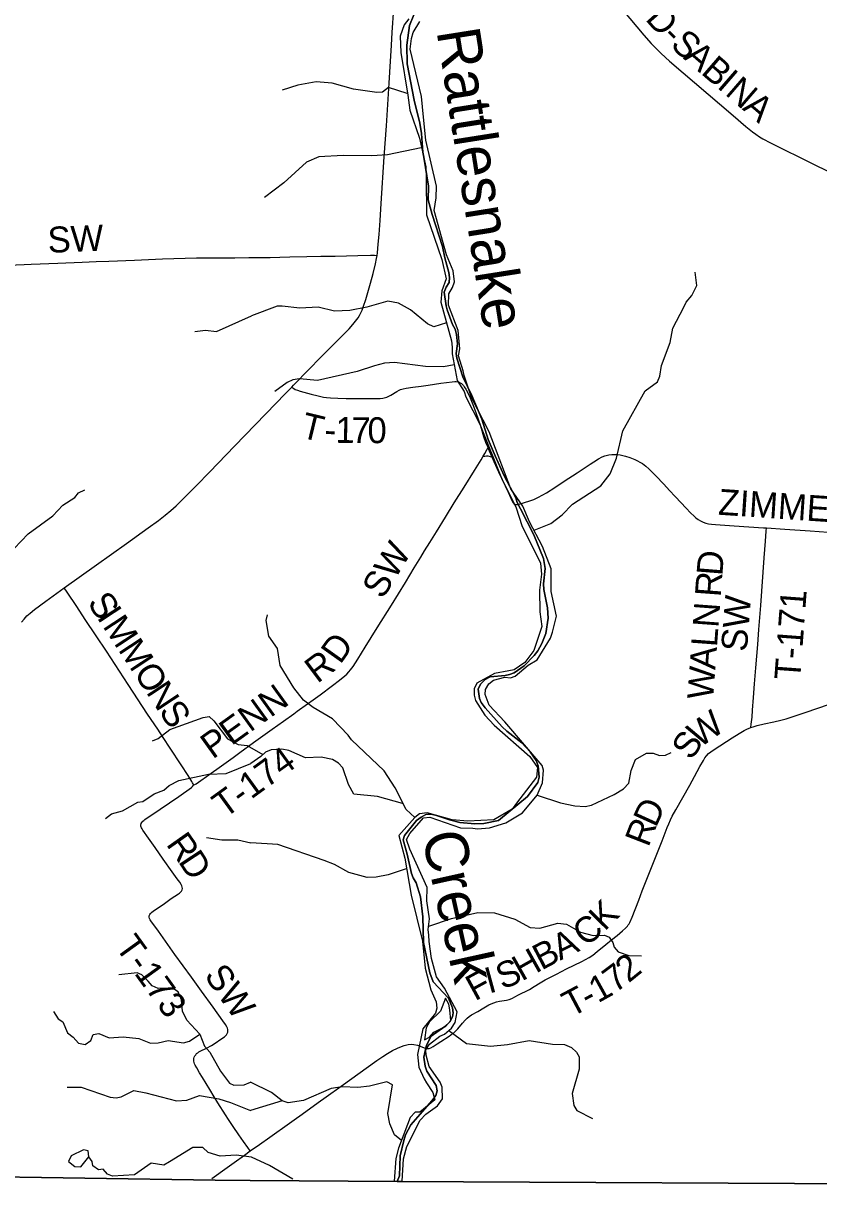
# Model space of a CAD drawing. Extents: x -51392 to 1635000, y 156707 to 696232.
# Drawn here: x 119003 to 128219, y 428826 to 442411 of the extents above; entities that cross this region are included whole.
import ezdxf

# ---------------------------------------------------------------- set-up
doc = ezdxf.new("R2010")
doc.units = 0
for name, color, linetype in [('GM_X_Adjacent_County', 7, 'Continuous'), ('GM_X_County', 7, 'Continuous'), ('GM_X_County_Road', 7, 'Continuous'), ('GM_X_County_Road_Text', 7, 'Continuous'), ('GM_X_Major_River', 7, 'Continuous'), ('GM_X_Major_River_Text', 7, 'Continuous'), ('GM_X_Minor_River', 7, 'Continuous'), ('GM_X_Township', 7, 'Continuous'), ('GM_X_Township_Road', 7, 'Continuous'), ('GM_X_Township_Road_Text', 7, 'Continuous')]:
    doc.layers.add(name, color=color, linetype=linetype)

msp = doc.modelspace()

# ---------------------------------------------------------------- linework, layer by layer
at = {"layer": 'GM_X_Adjacent_County'}
msp.add_lwpolyline([(104828, 429256), (108959, 429193), (114698, 429106), (118200, 429053), (121225, 429006), (121630, 429000), (123335, 428991), (129473, 428959), (134438, 428933), (140234, 428904), (140363, 428903), (142841, 428889), (147184, 428866), (150230, 428850), (152105, 428841), (155079, 428826)], dxfattribs=at)
at = {"layer": 'GM_X_County'}
msp.add_lwpolyline([(155079, 428826), (152105, 428841), (150230, 428850), (147184, 428866), (142841, 428889), (140363, 428903), (140234, 428904), (134438, 428933), (129473, 428959), (123335, 428991), (121630, 429000), (121225, 429006), (118200, 429053), (114698, 429106), (108959, 429193), (104828, 429256)], dxfattribs=at)
at = {"layer": 'GM_X_County_Road'}
for points in [[(123102, 439722), (123106, 439753), (123116, 439851), (123125, 439966), (123137, 440129), (123149, 440326), (123185, 440866), (123209, 441226), (123240, 441717), (123249, 441848), (123269, 442159), (123278, 442306), (123296, 442584)], [(125949, 442564), (126193, 442276), (126280, 442178), (126336, 442119), (126395, 442062), (126493, 441975), (127229, 441346), (127377, 441218), (127454, 441155), (127493, 441126), (127533, 441098), (127575, 441073), (127662, 441027), (128162, 440780), (128500, 440613)], [(122112, 438196), (122133, 438218), (122316, 438406), (122442, 438535), (122523, 438617), (122638, 438733), (122731, 438826), (122778, 438872), (122822, 438921), (122853, 438959), (122882, 439000), (122899, 439028), (122914, 439057), (122927, 439087), (122945, 439134), (122970, 439212), (123026, 439401), (123056, 439512), (123083, 439624), (123096, 439688), (123102, 439722)], [(119476, 435868), (119849, 436135), (120022, 436260), (120196, 436384), (120450, 436565), (120569, 436652), (120647, 436712), (120710, 436765), (120771, 436820), (120842, 436888), (121004, 437051), (121164, 437216), (121449, 437510), (121814, 437888), (122042, 438124), (122112, 438196)], [(118980, 435470), (119010, 435508), (119043, 435544), (119080, 435577), (119130, 435618), (119263, 435715), (119476, 435868)]]:
    msp.add_lwpolyline(points, dxfattribs=at)
at = {"layer": 'GM_X_Major_River'}
msp.add_line((123299, 428993), (123394, 428992), dxfattribs=at)
for points in [[(123468, 442466), (123414, 442396), (123370, 442262), (123377, 442075), (123457, 441578), (123483, 441405), (123592, 441081), (123666, 440748), (123672, 440620), (123673, 440193), (123854, 439676), (123904, 439451), (123851, 439313), (123842, 439179), (123966, 438733), (123974, 438658), (123971, 438582), (124030, 438271), (124111, 438146), (124131, 438082), (124292, 437766), (124543, 437142), (124712, 436796), (124779, 436593), (124995, 436154), (125008, 436028), (124984, 435843), (124990, 435593), (125013, 435420), (124918, 435144), (124815, 435003), (124692, 434920), (124629, 434908), (124461, 434877), (124258, 434765), (124229, 434701), (124228, 434627), (124244, 434563), (124349, 434395), (124460, 434280)], [(124400, 434511), (124355, 434632), (124357, 434690), (124398, 434756), (124452, 434801), (124581, 434836), (124647, 434826), (124703, 434845), (124854, 434972), (124959, 435036), (125113, 435287), (125134, 435355), (125182, 435543), (125118, 435826), (125121, 436089), (125021, 436348), (124867, 436636), (124790, 436815), (124654, 437019), (124505, 437405), (124402, 437679), (124197, 438077), (124113, 438330), (124099, 438383), (124045, 438558), (124060, 438640), (124041, 438852), (123928, 439144), (123933, 439278), (123976, 439352), (124000, 439416), (123983, 439544), (123905, 439731), (123765, 440244), (123787, 440390), (123792, 440526), (123666, 441059), (123641, 441325), (123617, 441564), (123485, 442113), (123500, 442235), (123521, 442307), (123596, 442434)], [(123394, 428992), (123408, 429251), (123445, 429395), (123602, 429701), (123665, 429768), (123802, 429867), (123861, 429947), (123856, 430083), (123833, 430142), (123704, 430323), (123669, 430454), (123668, 430516), (123710, 430582), (123829, 430673), (123883, 430695), (123964, 430768), (124007, 430832), (124030, 430954), (123882, 431230), (123789, 431363), (123733, 431574), (123707, 431769), (123701, 431845), (123694, 431909), (123711, 432033), (123677, 432244), (123682, 432396), (123480, 432841), (123443, 432954), (123483, 433023), (123639, 433203), (123713, 433210), (124069, 433089), (124213, 433083), (124267, 433077), (124405, 433088), (124594, 433146), (124787, 433263), (124957, 433468), (125021, 433608), (125032, 433758), (125016, 433810), (124584, 434317), (124400, 434511)], [(124460, 434280), (124871, 433916), (124960, 433789), (124949, 433677), (124718, 433376), (124667, 433306), (124454, 433180), (124154, 433166), (123971, 433180), (123682, 433262), (123594, 433249), (123539, 433207), (123355, 432998), (123423, 432737), (123495, 432306), (123629, 431773), (123660, 431462), (123724, 431211), (123785, 431072), (123794, 430998), (123779, 430940), (123632, 430759), (123569, 430461), (123584, 430316), (123647, 430181), (123676, 430131), (123747, 430020), (123773, 429936), (123597, 429793), (123543, 429791), (123486, 429732), (123349, 429374), (123318, 429256), (123299, 428993)], [(123893, 431113), (123836, 430964), (123708, 430838), (123672, 430769), (123653, 430630), (123711, 430662), (123758, 430722), (123868, 430773)], [(123868, 430773), (123896, 430787), (123955, 430856), (123946, 430979), (123935, 431045), (123893, 431113)]]:
    msp.add_lwpolyline(points, dxfattribs=at)
at = {"layer": 'GM_X_Minor_River'}
msp.add_line((123299, 428993), (123394, 428992), dxfattribs=at)
for points in [[(123451, 441599), (123233, 441668), (123164, 441614), (123098, 441611), (122828, 441651), (122581, 441719), (122395, 441735), (122184, 441697), (122001, 441636)], [(123614, 440971), (123222, 440890), (123040, 440875), (122707, 440880), (122427, 440867), (122284, 440804), (122022, 440563), (121796, 440395)], [(124922, 436540), (125117, 436616), (125248, 436717), (125367, 436838), (125696, 437052), (125803, 437192), (125877, 437373), (125952, 437689), (126208, 438154), (126351, 438259), (126380, 438323), (126397, 438445), (126499, 438713), (126531, 438881), (126657, 439123), (126684, 439181), (126749, 439258), (126810, 439374), (126787, 439529)], [(123906, 438943), (123759, 438893), (123688, 438929), (123491, 439092), (123351, 439171), (123227, 439194), (122982, 439122), (122786, 439083), (122609, 439077), (122418, 439123), (122205, 439110), (122003, 439134), (121943, 439133), (121645, 439023)], [(120988, 438839), (121112, 438857), (121239, 438841), (121645, 439023)], [(123996, 438456), (123871, 438431), (123663, 438435), (123305, 438480), (123187, 438473), (123072, 438444), (122870, 438377), (122410, 438273), (122202, 438293), (122124, 438279), (122061, 438250), (121916, 438145)], [(118895, 436327), (119056, 436495), (119342, 436704), (119460, 436828), (119597, 436918), (119641, 436972), (119715, 437004)], [(123539, 433207), (123438, 433302), (123312, 433550), (123185, 433748), (122806, 434108), (122768, 434164), (122586, 434350), (122361, 434482), (122247, 434569), (122136, 434709), (121978, 434971), (121948, 435167), (121847, 435309), (121817, 435493), (121831, 435555)], [(120497, 434095), (120563, 434125), (120699, 434227), (121086, 434366), (121154, 434378), (121208, 434330), (121368, 434118), (121490, 434054), (121596, 434044)], [(121596, 434044), (121776, 433938), (121774, 433940)], [(121668, 434041), (121668, 434041)], [(123398, 433370), (123107, 433450), (122833, 433478), (122771, 433589), (122703, 433784), (122655, 433838), (122586, 433879), (122454, 433908), (122273, 433900), (122078, 433986), (121998, 434000), (121874, 433993), (121807, 433966), (121753, 433916), (121637, 433833)], [(124957, 433468), (125229, 433377), (125393, 433344), (125515, 433337), (125587, 433350), (125851, 433474), (125959, 433540), (126018, 433607), (126047, 433751), (126096, 433879), (126223, 433954), (126301, 433954), (126375, 433927), (126443, 433932), (126510, 433962)], [(119953, 433196), (120024, 433252), (120150, 433284), (120328, 433386), (120386, 433394), (120518, 433482), (120630, 433524), (120693, 433578), (120803, 433636), (121149, 433711), (121353, 433719), (121637, 433833)], [(121126, 432976), (121304, 432950), (121488, 432950), (121637, 432914)], [(121565, 432927), (121564, 432927)], [(123438, 432615), (123231, 432544), (123092, 432518), (122986, 432514), (122776, 432570), (122607, 432664), (122489, 432709), (121950, 432894), (121637, 432914)], [(123700, 431948), (123963, 432039), (124268, 432107), (124463, 432105), (124698, 432031), (124876, 431935), (124988, 431924), (125195, 431983), (125299, 431972), (125458, 431878), (125606, 431841), (125738, 431846), (125792, 431821), (125835, 431759), (125849, 431706), (125895, 431652), (126018, 431609), (126168, 431603)], [(121049, 430695), (120897, 430859), (120845, 430963), (120833, 431094), (120797, 431186), (120729, 431230), (120563, 431228), (120495, 431256), (120447, 431310), (120375, 431384), (120319, 431407), (120107, 431385)], [(119350, 430961), (119404, 430875), (119458, 430838), (119512, 430714), (119580, 430664), (119642, 430592), (119718, 430576), (119782, 430624), (119812, 430694), (119878, 430704), (119996, 430656), (120158, 430666), (120340, 430645), (120476, 430591), (120564, 430597), (120682, 430623), (120856, 430595), (120926, 430617), (121049, 430695), (121103, 430559), (121164, 430488), (121288, 430270), (121390, 430130), (121442, 430104), (121560, 430111), (121635, 430139)], [(123933, 430738), (124139, 430590), (124415, 430558), (124613, 430576), (124866, 430624), (125136, 430580), (125276, 430579), (125356, 430542), (125414, 430487), (125443, 430433), (125446, 430290), (125363, 430008), (125382, 429870), (125418, 429814), (125599, 429720)], [(123383, 429463), (123304, 429531), (123251, 429658), (123228, 429776), (123279, 430110), (123214, 430145), (123015, 430093), (122877, 430078), (122698, 430085), (122570, 430068), (122250, 429927), (122070, 429902), (122002, 429925), (121877, 430022), (121635, 430139)], [(119509, 430081), (119671, 430081), (120009, 429967), (120077, 429959), (120135, 429971), (120283, 430044), (120421, 430018), (120775, 429926), (120895, 429932), (121044, 429986), (121266, 429947), (121404, 429905), (121636, 429813)], [(122002, 429925), (121636, 429813)], [(121646, 429271), (121467, 429296), (121281, 429282), (121143, 429327), (121083, 429383), (120967, 429385), (120696, 429219), (120630, 429177), (120482, 429201), (120288, 429067), (120034, 429053), (119976, 429075), (119926, 429133), (119874, 429123), (119808, 429170), (119798, 429222), (119760, 429276), (119752, 429346), (119698, 429358), (119554, 429288), (119525, 429222), (119599, 429162), (119669, 429160), (119760, 429276)], [(122126, 429016), (121855, 429176), (121646, 429271)]]:
    msp.add_lwpolyline(points, dxfattribs=at)
at = {"layer": 'GM_X_Township'}
for points in [[(123526, 442511), (123479, 442389), (123446, 442159), (123452, 441941), (123533, 441520), (123596, 441255), (123616, 441135), (123631, 440918), (123643, 440860), (123696, 440527), (123693, 440367), (123741, 440195), (123860, 439826), (123886, 439695), (123933, 439525), (123941, 439465), (123937, 439407), (123903, 439353), (123880, 439295), (123902, 439140), (123914, 439090), (123977, 438920), (124005, 438866), (124021, 438805), (124035, 438699), (124019, 438585), (124026, 438531), (124096, 438316), (124199, 438098), (124315, 437825), (124388, 437590), (124470, 437398), (124575, 437167), (124709, 436912), (124727, 436858), (124763, 436786), (124918, 436485), (125031, 436208), (125051, 436095), (125032, 435917), (125034, 435849), (125079, 435639), (125083, 435518), (125056, 435340), (125012, 435224), (124964, 435138), (124923, 435086), (124807, 434964), (124692, 434886), (124638, 434865), (124588, 434855), (124414, 434839), (124356, 434807), (124301, 434755), (124273, 434695), (124287, 434589), (124307, 434539), (124355, 434479), (124552, 434260), (124606, 434208), (124778, 434073), (124876, 433970), (124912, 433920), (124944, 433868), (124968, 433808), (124981, 433675), (124967, 433613), (124846, 433450), (124511, 433172), (124338, 433137), (124236, 433133), (124062, 433149), (123940, 433180), (123778, 433237), (123725, 433245), (123665, 433241), (123611, 433213), (123557, 433173), (123420, 433001), (123404, 432949), (123450, 432785), (123499, 432560), (123519, 432510), (123555, 432452), (123604, 432287), (123632, 432057), (123639, 431758), (123712, 431408), (123752, 431305), (123929, 431114), (123975, 431002), (123983, 430946), (123977, 430896), (123945, 430840), (123888, 430784), (123728, 430674), (123673, 430570), (123656, 430483), (123645, 430430), (123660, 430326), (123678, 430270), (123786, 430103), (123800, 430039), (123782, 429985), (123735, 429925), (123494, 429645), (123433, 429531), (123411, 429465), (123371, 429287), (123362, 429055), (123335, 428991), (121630, 429000), (121225, 429006), (118200, 429053)], [(129473, 428959), (123335, 428991), (123362, 429055), (123371, 429287), (123411, 429465), (123433, 429531), (123494, 429645), (123735, 429925), (123782, 429985), (123800, 430039), (123786, 430103), (123678, 430270), (123660, 430326), (123645, 430430), (123656, 430483), (123673, 430570), (123728, 430674), (123888, 430784), (123945, 430840), (123977, 430896), (123983, 430946), (123975, 431002), (123929, 431114), (123752, 431305), (123712, 431408), (123639, 431758), (123632, 432057), (123604, 432287), (123555, 432452), (123519, 432510), (123499, 432560), (123450, 432785), (123404, 432949), (123420, 433001), (123557, 433173), (123611, 433213), (123665, 433241), (123725, 433245), (123778, 433237), (123940, 433180), (124062, 433149), (124236, 433133), (124338, 433137), (124511, 433172), (124846, 433450), (124967, 433613), (124981, 433675), (124968, 433808), (124944, 433868), (124912, 433920), (124876, 433970), (124778, 434073), (124606, 434208), (124552, 434260), (124355, 434479), (124307, 434539), (124287, 434589), (124273, 434695), (124301, 434755), (124356, 434807), (124414, 434839), (124588, 434855), (124638, 434865), (124692, 434886), (124807, 434964), (124923, 435086), (124964, 435138), (125012, 435224), (125056, 435340), (125083, 435518), (125079, 435639), (125034, 435849), (125032, 435917), (125051, 436095), (125031, 436208), (124918, 436485), (124763, 436786), (124727, 436858), (124709, 436912), (124575, 437167), (124470, 437398), (124388, 437590), (124315, 437825), (124199, 438098), (124096, 438316), (124026, 438531), (124019, 438585), (124035, 438699), (124021, 438805), (124005, 438866), (123977, 438920), (123914, 439090), (123902, 439140), (123880, 439295), (123903, 439353), (123937, 439407), (123941, 439465), (123933, 439525), (123886, 439695), (123860, 439826), (123741, 440195), (123693, 440367), (123696, 440527), (123643, 440860), (123631, 440918), (123616, 441135), (123596, 441255), (123533, 441520), (123452, 441941), (123446, 442159), (123479, 442389), (123526, 442511)]]:
    msp.add_lwpolyline(points, dxfattribs=at)
at = {"layer": 'GM_X_Township_Road'}
for points in [[(118732, 439606), (119010, 439618), (119092, 439621), (119403, 439634), (119682, 439645), (119846, 439652), (119993, 439657), (120288, 439667), (120452, 439675), (120616, 439681), (120878, 439691), (121009, 439694), (121206, 439695), (121451, 439696), (121615, 439697), (121861, 439699), (121976, 439703), (122090, 439706), (122287, 439710), (122451, 439713), (122615, 439715), (122746, 439719), (122877, 439723), (123024, 439726), (123072, 439727), (123102, 439722)], [(122112, 438196), (122136, 438180), (122153, 438170), (122180, 438159), (122212, 438149), (122338, 438114), (122417, 438094), (122481, 438079), (122514, 438074), (122563, 438070), (122645, 438067), (122743, 438066), (122890, 438066), (123005, 438064), (123087, 438064), (123136, 438065), (123169, 438069), (123185, 438072), (123216, 438081), (123231, 438088), (123260, 438102), (123330, 438146), (123359, 438161), (123374, 438168), (123389, 438173), (123405, 438178), (123437, 438185), (123517, 438197), (123614, 438208), (123695, 438220), (123841, 438241), (123971, 438258), (124004, 438261), (124020, 438261), (124036, 438259), (124052, 438254), (124066, 438247), (124080, 438238), (124092, 438227), (124103, 438214), (124113, 438201), (124130, 438173), (124160, 438115), (124181, 438071), (124212, 437995), (124247, 437903), (124275, 437826), (124300, 437748), (124337, 437622), (124359, 437560), (124384, 437500), (124387, 437494)], [(124333, 437395), (124351, 437426), (124374, 437469), (124387, 437494)], [(124387, 437494), (124433, 437387)], [(120973, 433586), (120988, 433590), (121005, 433597), (121180, 433722), (121273, 433789), (121432, 433904), (121512, 433962), (121671, 434077), (121751, 434134), (121884, 434230), (122017, 434326), (122137, 434411), (122176, 434440), (122295, 434526), (122362, 434573), (122442, 434631), (122586, 434738), (122665, 434798), (122728, 434850), (122752, 434871), (122775, 434895), (122795, 434920), (122824, 434960), (122877, 435043), (122964, 435182), (123103, 435405), (123268, 435669), (123432, 435933), (123483, 436017), (123533, 436101), (123610, 436227), (123653, 436297), (123713, 436394), (123790, 436520), (123894, 436687), (123997, 436854), (124110, 437036), (124232, 437230), (124309, 437355), (124333, 437395)], [(124333, 437395), (124352, 437397), (124371, 437399), (124387, 437398), (124412, 437393), (124433, 437387)], [(124433, 437387), (124456, 437335), (124509, 437214), (124550, 437125), (124622, 436978), (124669, 436873), (124677, 436859), (124687, 436846), (124701, 436837), (124717, 436834), (124733, 436835), (124741, 436838)], [(124741, 436838), (124749, 436840), (124874, 436878), (124920, 436895), (124965, 436916), (125022, 436947), (125065, 436972), (125161, 437034), (125270, 437106), (125421, 437204), (125504, 437256), (125572, 437302), (125613, 437329), (125668, 437364), (125711, 437388), (125741, 437400), (125773, 437409), (125789, 437412), (125821, 437416), (125854, 437417), (125887, 437415), (125919, 437410), (125951, 437403), (125983, 437395), (126030, 437379), (126091, 437356), (126121, 437343), (126149, 437327), (126177, 437310), (126216, 437280), (126252, 437248), (126288, 437214), (126334, 437167), (126424, 437071), (126490, 436999), (126557, 436927), (126625, 436856), (126681, 436797), (126738, 436737), (126773, 436703), (126798, 436682), (126824, 436662), (126852, 436645), (126882, 436632), (126913, 436621), (126945, 436613), (126977, 436607), (127026, 436602), (127239, 436590), (127582, 436567), (127614, 436565)], [(127435, 434250), (127439, 434290), (127448, 434371), (127455, 434453), (127466, 434598), (127478, 434756), (127493, 434943), (127514, 435215), (127527, 435385), (127549, 435667), (127589, 436216), (127603, 436412), (127612, 436526), (127614, 436565)], [(127614, 436565), (127828, 436550), (128122, 436529), (128433, 436507), (128923, 436470), (129103, 436457), (129446, 436432), (129659, 436417), (129871, 436404), (130068, 436392), (130362, 436375), (130542, 436363), (130657, 436357), (130935, 436340), (131000, 436335), (131049, 436327), (131080, 436320), (131112, 436309), (131157, 436290), (131231, 436254), (131333, 436202), (131494, 436117)], [(120973, 433586), (120973, 433592), (120971, 433597), (120964, 433611), (120955, 433625), (120911, 433694), (120830, 433818), (120704, 434010), (120623, 434134), (120560, 434230), (120441, 434407), (120217, 434750), (120064, 434983), (119964, 435134), (119847, 435312), (119720, 435504), (119621, 435654), (119511, 435818), (119476, 435868)], [(127435, 434250), (127462, 434260), (127509, 434274), (127589, 434293), (127702, 434317), (127782, 434335), (127845, 434352), (127923, 434377), (128063, 434424), (128482, 434568)], [(123669, 430532), (123687, 430529), (123704, 430531), (123724, 430537), (123753, 430553), (123800, 430586), (123842, 430611), (123937, 430675), (123977, 430704), (123990, 430714), (124014, 430736), (124037, 430760), (124090, 430823), (124123, 430859), (124146, 430882), (124171, 430902), (124198, 430920), (124270, 430960), (124340, 431001), (124397, 431035), (124426, 431049), (124456, 431061), (124487, 431071), (124519, 431078), (124600, 431091), (124632, 431100), (124662, 431112), (124706, 431134), (124735, 431150), (124867, 431216), (124924, 431248), (124993, 431292), (125050, 431325), (125181, 431393), (125298, 431453), (125475, 431538), (125519, 431561), (125561, 431586), (125602, 431614), (125653, 431654), (125755, 431738), (125819, 431789), (125883, 431840), (125946, 431893), (125982, 431926), (126004, 431950), (126014, 431963), (126023, 431977), (126031, 431991), (126057, 432051), (126135, 432250), (126176, 432357), (126261, 432571), (126405, 432937), (126464, 433091), (126482, 433136), (126502, 433181), (126524, 433225), (126564, 433297), (126647, 433438), (126728, 433581), (126782, 433683), (126844, 433799), (126884, 433870), (126902, 433898), (126922, 433924), (126944, 433948), (126969, 433969), (127010, 433997), (127217, 434130), (127300, 434182), (127357, 434216), (127386, 434231), (127416, 434244), (127435, 434250)], [(121629, 429343), (121603, 429382), (121555, 429451), (121499, 429531), (121434, 429626), (121380, 429708), (121344, 429763), (121257, 429902), (121214, 429972), (121163, 430056), (121079, 430194), (121045, 430249), (121011, 430307), (120995, 430336), (120987, 430352), (120982, 430368), (120978, 430383), (120977, 430399), (120979, 430415), (120983, 430431), (120990, 430446), (120999, 430459), (121010, 430471), (121023, 430482), (121036, 430491), (121051, 430499), (121125, 430534), (121182, 430566), (121224, 430591), (121292, 430638), (121332, 430667), (121344, 430678), (121355, 430690), (121364, 430704), (121370, 430719), (121372, 430735), (121371, 430751), (121367, 430767), (121360, 430782), (121343, 430810), (121314, 430850), (121201, 431009), (121067, 431195), (120952, 431358), (120758, 431622), (120567, 431889), (120480, 432009), (120472, 432023), (120465, 432038), (120461, 432053), (120461, 432069), (120466, 432085), (120474, 432095), (120486, 432107), (120511, 432125), (120566, 432163), (120636, 432212), (120716, 432268), (120799, 432322), (120812, 432332), (120824, 432343), (120834, 432356), (120841, 432369), (120845, 432385), (120844, 432401), (120839, 432416), (120832, 432431), (120814, 432459), (120784, 432498), (120727, 432579), (120623, 432726), (120528, 432860), (120453, 432967), (120386, 433061), (120377, 433075), (120370, 433090), (120365, 433106), (120364, 433121), (120367, 433137), (120374, 433151), (120385, 433164), (120397, 433175), (120410, 433185), (120587, 433304), (120804, 433452), (120952, 433556), (120964, 433567), (120972, 433581), (120973, 433586)], [(121629, 429343), (121738, 429418), (121859, 429503), (122086, 429665), (122139, 429703), (122233, 429770), (122419, 429904), (122512, 429971), (122685, 430096), (123099, 430392), (123167, 430438), (123222, 430474), (123279, 430506), (123339, 430534), (123384, 430553), (123415, 430565), (123446, 430573), (123463, 430576), (123495, 430580), (123529, 430577), (123570, 430569), (123660, 430534), (123669, 430532)], [(121186, 429023), (121364, 429151), (121444, 429208), (121564, 429295), (121629, 429343)]]:
    msp.add_lwpolyline(points, dxfattribs=at)

# ---------------------------------------------------------------- texts
at = {"layer": 'GM_X_County_Road_Text'}
for s, rotation, p in [('D', 311.498, (126202, 442458)), ('-', 314.9998, (126390, 442246)), ('S', 317.9922, (126490, 442147)), ('A', 319.1695, (126645, 442007)), ('B', 319.1646, (126845, 441835)), ('I', 319.1642, (127031, 441674)), ('N', 319.1695, (127125, 441593)), ('A', 319.588, (127326, 441419))]:
    msp.add_text(s, height=300, rotation=rotation, dxfattribs=at).set_placement(p)
at = {"layer": 'GM_X_Major_River_Text'}
for s, rotation, p in [('Rattlesnake', 278.9942, (123790, 442323)), ('Creek', 282.5101, (123617, 433003))]:
    msp.add_text(s, height=500, rotation=rotation, dxfattribs=at).set_placement(p)
at = {"layer": 'GM_X_Township_Road_Text'}
for s, rotation, p in [('SW', 2.3676, (119289, 439752)), ('T', 346.3454, (122203, 437616)), ('1', 359.181, (122617, 437551)), ('7', 359.2613, (122802, 437548)), ('0', 0.1058, (122991, 437546)), ('-', 358.5495, (122490, 437554)), ('ZIMMERMAN RD SW', 356.1827, (127050, 436718)), ('SW', 58.4762, (123166, 435728)), ('D', 85.4503, (127103, 436003)), ('R', 85.7597, (127084, 435758)), ('S', 303.3549, (119736, 435698)), ('T-171', 85.7759, (128005, 434794)), ('I', 303.354, (119847, 435529)), ('N', 85.761, (127058, 435402)), ('SW', 85.5101, (127387, 435124)), ('M', 303.3538, (119915, 435426)), ('L', 85.7652, (127041, 435179)), ('M', 303.3545, (120094, 435154)), ('D', 54.574, (122675, 434974)), ('R', 36.9565, (122409, 434755)), ('A', 85.7628, (127022, 434915)), ('O', 303.3537, (120273, 434882)), ('W', 85.7605, (126996, 434569)), ('N', 303.3668, (120418, 434661)), ('PENN', 35.7431, (121196, 433878)), ('S', 303.7789, (120564, 434439)), ('W', 35.2749, (126838, 434007)), ('S', 55.8772, (126744, 433860)), ('T-174', 35.9171, (121334, 433191)), ('D', 65.5718, (126333, 433081)), ('R', 68.8089, (126246, 432855)), ('R', 305.2246, (120649, 432898)), ('D', 303.5487, (120790, 432698)), ('K', 45.2745, (125740, 431881)), ('C', 38.5977, (125519, 431701)), ('T-173', 305.8042, (120058, 431710)), ('A', 26.3607, (125224, 431547)), ('B', 27.5714, (125007, 431433)), ('H', 29.4078, (124779, 431305)), ('2', 39.0175, (126017, 431284)), ('SW', 305.1188, (121090, 431375)), ('F', 28.6124, (124237, 431076)), ('I', 15.2507, (124398, 431166)), ('S', 21.9089, (124553, 431211)), ('7', 36.9462, (125861, 431167)), ('1', 28.9643, (125662, 431053)), ('T', 27.9131, (125351, 430888)), ('-', 27.98, (125549, 430993))]:
    msp.add_text(s, height=300, rotation=rotation, dxfattribs=at).set_placement(p)

doc.saveas('drawing.dxf')
